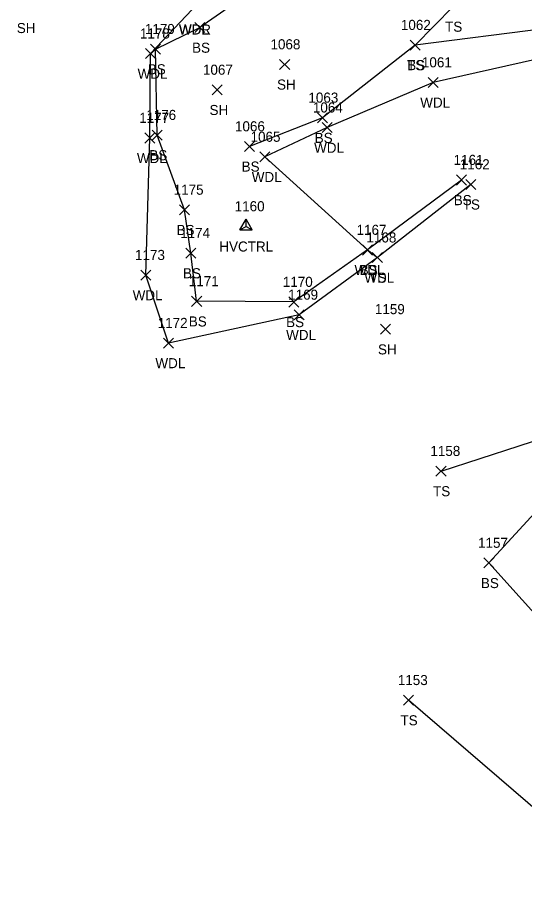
# Model space of a CAD drawing. Extents: x 1879695 to 1880991, y 836466 to 845172.
# Drawn here: x 1879695.5 to 1879796.4, y 844202.8 to 844375.9 of the extents above; entities that cross this region are included whole.
import ezdxf

# ---------------------------------------------------------------- set-up
doc = ezdxf.new("R2010")
doc.units = 0
for name, color, linetype in [('C_A', 7, 'Continuous'), ('C_I', 7, 'Continuous'), ('CPSM', 7, 'Continuous'), ('L_A', 7, 'Continuous'), ('L_I', 7, 'Continuous'), ('L_TIC', 7, 'Continuous'), ('LAWA', 7, 'Continuous'), ('LELB', 7, 'Continuous')]:
    doc.layers.add(name, color=color, linetype=linetype)

msp = doc.modelspace()

# ---------------------------------------------------------------- linework, layer by layer
at = {"layer": 'CPSM'}
for p, q in [((1879739.73, 844333.66), (1879740.98, 844335.82)), ((1879742.23, 844333.66), (1879740.98, 844335.82)), ((1879740.98, 844334.38), (1879740.98, 844335.82)), ((1879739.73, 844333.66), (1879740.98, 844334.38)), ((1879739.73, 844333.66), (1879742.23, 844333.66)), ((1879740.98, 844334.38), (1879740.98, 844334.38)), ((1879740.98, 844334.38), (1879742.23, 844333.66))]:
    msp.add_line(p, q, dxfattribs=at)
at = {"layer": 'L_TIC'}
for points in [[(1879730.81, 844372.87), (1879732.81, 844374.87)], [(1879732.81, 844372.87), (1879730.81, 844374.87)], [(1879730.81, 844372.87), (1879732.81, 844374.87)], [(1879732.81, 844372.87), (1879730.81, 844374.87)], [(1879722, 844368.59), (1879724, 844370.59)], [(1879724, 844368.59), (1879722, 844370.59)], [(1879773.59, 844369.4), (1879775.59, 844371.4)], [(1879775.59, 844369.4), (1879773.59, 844371.4)], [(1879773.59, 844369.4), (1879775.59, 844371.4)], [(1879775.59, 844369.4), (1879773.59, 844371.4)], [(1879721.01, 844367.7), (1879723.01, 844369.7)], [(1879723.01, 844367.7), (1879721.01, 844369.7)], [(1879747.66, 844365.55), (1879749.66, 844367.55)], [(1879749.66, 844365.55), (1879747.66, 844367.55)], [(1879777.2, 844361.97), (1879779.2, 844363.97)], [(1879779.2, 844361.97), (1879777.2, 844363.97)], [(1879734.23, 844360.5), (1879736.23, 844362.5)], [(1879736.23, 844360.5), (1879734.23, 844362.5)], [(1879755.19, 844354.96), (1879757.19, 844356.96)], [(1879757.19, 844354.96), (1879755.19, 844356.96)], [(1879756.09, 844353), (1879758.09, 844355)], [(1879758.09, 844353), (1879756.09, 844355)], [(1879720.87, 844350.94), (1879722.87, 844352.94)], [(1879722.87, 844350.94), (1879720.87, 844352.94)], [(1879722.31, 844351.52), (1879724.31, 844353.52)], [(1879724.31, 844351.52), (1879722.31, 844353.52)], [(1879740.66, 844349.26), (1879742.66, 844351.26)], [(1879742.66, 844349.26), (1879740.66, 844351.26)], [(1879743.7, 844347.18), (1879745.7, 844349.18)], [(1879745.7, 844347.18), (1879743.7, 844349.18)], [(1879782.85, 844342.59), (1879784.85, 844344.59)], [(1879784.85, 844342.59), (1879782.85, 844344.59)], [(1879784.66, 844341.72), (1879786.66, 844343.72)], [(1879786.66, 844341.72), (1879784.66, 844343.72)], [(1879727.72, 844336.66), (1879729.72, 844338.66)], [(1879729.72, 844336.66), (1879727.72, 844338.66)], [(1879764.14, 844328.69), (1879766.14, 844330.69)], [(1879766.14, 844328.69), (1879764.14, 844330.69)], [(1879764.14, 844328.69), (1879766.14, 844330.69)], [(1879766.14, 844328.69), (1879764.14, 844330.69)], [(1879729, 844328.07), (1879731, 844330.07)], [(1879731, 844328.07), (1879729, 844330.07)], [(1879766.09, 844327.18), (1879768.09, 844329.18)], [(1879768.09, 844327.18), (1879766.09, 844329.18)], [(1879766.09, 844327.18), (1879768.09, 844329.18)], [(1879768.09, 844327.18), (1879766.09, 844329.18)], [(1879720.03, 844323.7), (1879722.03, 844325.7)], [(1879722.03, 844323.7), (1879720.03, 844325.7)], [(1879730.16, 844318.49), (1879732.16, 844320.49)], [(1879732.16, 844318.49), (1879730.16, 844320.49)], [(1879749.51, 844318.36), (1879751.51, 844320.36)], [(1879751.51, 844318.36), (1879749.51, 844320.36)], [(1879750.53, 844315.81), (1879752.53, 844317.81)], [(1879752.53, 844315.81), (1879750.53, 844317.81)], [(1879767.73, 844312.94), (1879769.73, 844314.94)], [(1879769.73, 844312.94), (1879767.73, 844314.94)], [(1879724.54, 844310.2), (1879726.54, 844312.2)], [(1879726.54, 844310.2), (1879724.54, 844312.2)], [(1879778.75, 844284.77), (1879780.75, 844286.77)], [(1879780.75, 844284.77), (1879778.75, 844286.77)], [(1879788.24, 844266.52), (1879790.24, 844268.52)], [(1879790.24, 844266.52), (1879788.24, 844268.52)], [(1879772.28, 844239.26), (1879774.28, 844241.26)], [(1879774.28, 844239.26), (1879772.28, 844241.26)]]:
    msp.add_lwpolyline(points, dxfattribs=at)
at = {"layer": 'LAWA'}
msp.add_lwpolyline([(1879819.57, 844382.71), (1879804.42, 844368.86), (1879778.2, 844362.97), (1879757.09, 844354), (1879744.7, 844348.18), (1879765.14, 844329.69), (1879767.09, 844328.18), (1879751.53, 844316.81), (1879725.54, 844311.2), (1879721.03, 844324.7), (1879721.87, 844351.94), (1879722.01, 844368.7), (1879730.25, 844377.49)], dxfattribs=at)
at = {"layer": 'LELB'}
for points in [[(1880002.51, 844242.73), (1879985.64, 844257.52), (1879965.17, 844278.62), (1879940.72, 844305.37), (1879925.82, 844326.46), (1879896.67, 844370.14), (1879885.64, 844389.62), (1879876.9, 844403.13), (1879868.08, 844418.79), (1879858.9, 844415.1), (1879849.52, 844405.96), (1879835.24, 844394.65), (1879817.98, 844385.29), (1879800.66, 844373.71), (1879774.59, 844370.4), (1879756.19, 844355.96), (1879741.66, 844350.26)], [(1879774.59, 844370.4), (1879782.15, 844378.04), (1879801.15, 844384.52), (1879812.02, 844396.53), (1879820.09, 844401.43), (1879825.03, 844409.82)], [(1879753.64, 844389.12), (1879731.81, 844373.87)], [(1879783.85, 844343.59), (1879765.14, 844329.69), (1879750.51, 844319.36), (1879731.16, 844319.49), (1879730, 844329.07), (1879728.72, 844337.66), (1879723.31, 844352.52), (1879723, 844369.59), (1879731.81, 844373.87)], [(1879785.66, 844342.72), (1879767.09, 844328.18)], [(1879779.75, 844285.77), (1879818.53, 844298.3)], [(1879856.87, 844231.08), (1879838.42, 844207.88), (1879818.44, 844213.69), (1879819.41, 844238.78), (1879809.17, 844245.49), (1879789.24, 844267.52), (1879810.46, 844290.57)], [(1879839.4, 844202.83), (1879815.05, 844204.4), (1879773.28, 844240.26)]]:
    msp.add_lwpolyline(points, dxfattribs=at)

# ---------------------------------------------------------------- texts
at = {"layer": 'C_A'}
msp.add_text('HVCTRL', height=2, dxfattribs=at).set_placement((1879735.67, 844329.38))
at = {"layer": 'C_I'}
msp.add_text('1160', height=2, dxfattribs=at).set_placement((1879738.72, 844337.38))
at = {"layer": 'L_A'}
for s, p in [('SH', (1879695.4, 844372.78)), ('WDR', (1879727.61, 844372.49)), ('WDL', (1879727.67, 844372.49)), ('TS', (1879780.56, 844373.04)), ('BS', (1879730.25, 844368.87)), ('BS', (1879730.25, 844368.87)), ('BS', (1879721.45, 844364.59)), ('TS', (1879773, 844365.4)), ('BS', (1879773.03, 844365.4)), ('WDL', (1879719.42, 844363.7)), ('SH', (1879747.15, 844361.55)), ('WDL', (1879775.62, 844357.97)), ('SH', (1879733.72, 844356.5)), ('BS', (1879754.63, 844350.96)), ('WDL', (1879754.51, 844349)), ('BS', (1879721.75, 844347.52)), ('WDL', (1879719.29, 844346.94)), ('BS', (1879740.1, 844345.26)), ('WDL', (1879742.12, 844343.18)), ('BS', (1879782.29, 844338.59)), ('TS', (1879784.07, 844337.72)), ('BS', (1879727.16, 844332.66)), ('BS', (1879763.58, 844324.69)), ('BS', (1879728.44, 844324.07)), ('WDL', (1879762.55, 844324.69)), ('WDL', (1879764.51, 844323.18)), ('TS', (1879765.5, 844323.18)), ('WDL', (1879718.44, 844319.7)), ('BS', (1879729.6, 844314.49)), ('BS', (1879748.95, 844314.36)), ('WDL', (1879748.95, 844311.81)), ('SH', (1879767.22, 844308.94)), ('WDL', (1879722.96, 844306.2)), ('TS', (1879778.16, 844280.77)), ('BS', (1879787.68, 844262.52)), ('TS', (1879771.69, 844235.26))]:
    msp.add_text(s, height=2, dxfattribs=at).set_placement(p)
at = {"layer": 'L_I'}
for s, p in [('1062', (1879771.77, 844373.4)), ('1062', (1879771.77, 844373.4)), ('1178', (1879719.88, 844371.7)), ('1179', (1879720.87, 844372.59)), ('1068', (1879745.84, 844369.55)), ('1067', (1879732.41, 844364.5)), ('1061', (1879775.95, 844365.97)), ('1063', (1879753.38, 844358.96)), ('1064', (1879754.27, 844357)), ('1177', (1879719.74, 844354.94)), ('1176', (1879721.13, 844355.52)), ('1066', (1879738.78, 844353.26)), ('1065', (1879741.88, 844351.18)), ('1161', (1879782.25, 844346.59)), ('1162', (1879783.48, 844345.72)), ('1175', (1879726.59, 844340.66)), ('1174', (1879727.88, 844332.07)), ('1167', (1879762.96, 844332.69)), ('1167', (1879762.96, 844332.69)), ('1168', (1879764.92, 844331.18)), ('1168', (1879764.92, 844331.18)), ('1173', (1879718.9, 844327.7)), ('1171', (1879729.6, 844322.49)), ('1170', (1879748.29, 844322.36)), ('1169', (1879749.35, 844319.81)), ('1159', (1879766.6, 844316.94)), ('1172', (1879723.41, 844314.2)), ('1158', (1879777.63, 844288.77)), ('1157', (1879787.11, 844270.52)), ('1153', (1879771.16, 844243.26))]:
    msp.add_text(s, height=2, dxfattribs=at).set_placement(p)

doc.saveas('drawing.dxf')
